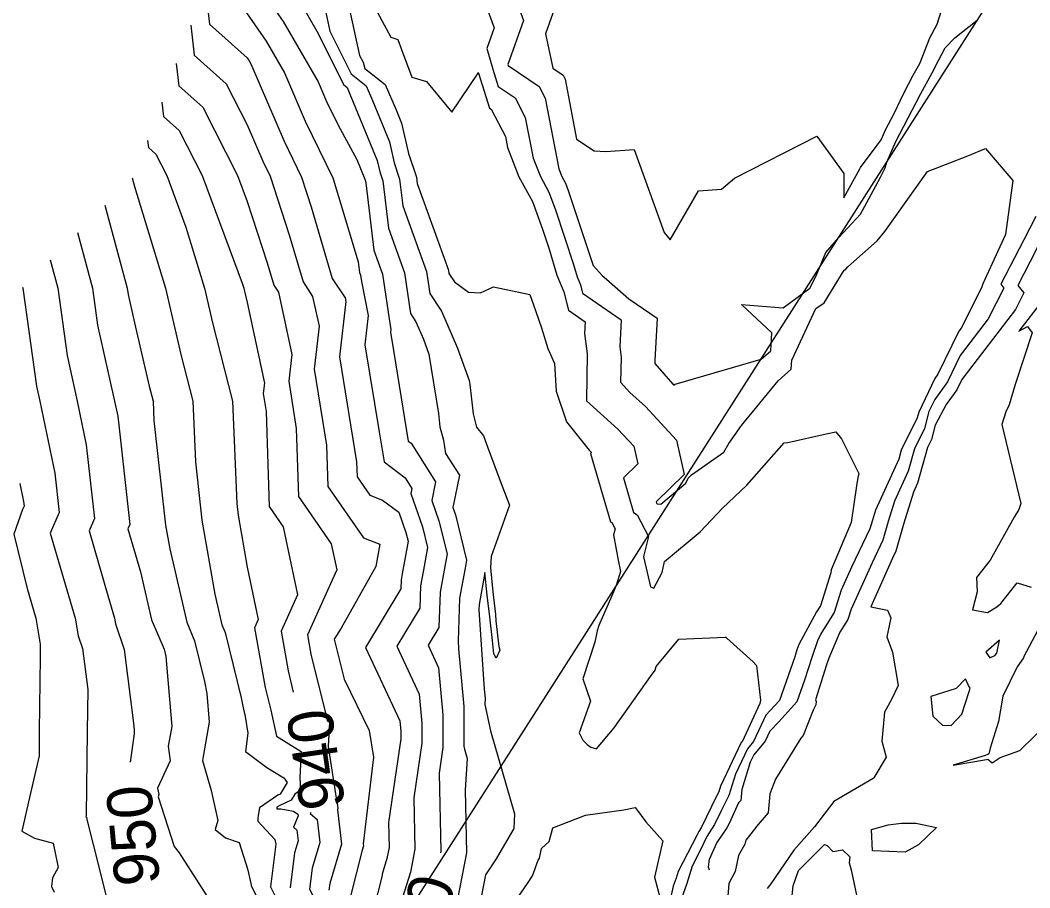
# Model space of a CAD drawing. Extents: x 1368651 to 1378602, y 762048 to 779328.
# Drawn here: x 1376956.1 to 1377179.9, y 762773.1 to 762965.4 of the extents above; entities that cross this region are included whole.
import ezdxf

# ---------------------------------------------------------------- set-up
doc = ezdxf.new("R2010")
doc.units = 0
for name, color, linetype in [('DTM Contours Major', 7, 'Continuous'), ('DTM Contours Major Text', 7, 'Continuous'), ('DTM Contours Minor', 7, 'Continuous'), ('Exist Plan Preparation Watershed Red', 7, 'Continuous')]:
    doc.layers.add(name, color=color, linetype=linetype)

msp = doc.modelspace()

# ---------------------------------------------------------------- linework, layer by layer
at = {"layer": 'DTM Contours Major'}
for points in [[(1377006.09, 762976.98), (1377014.37, 762965.06), (1377022.14, 762951.75), (1377024.01, 762947.39), (1377026.57, 762942.15), (1377030.74, 762934.5), (1377032.51, 762930.17), (1377032.62, 762929.71), (1377032.74, 762929.34), (1377034.51, 762914.39), (1377036.41, 762909.12), (1377038.08, 762897.71), (1377038.25, 762896.87), (1377038.17, 762896.15), (1377038.52, 762894), (1377042.1, 762872.08), (1377042.74, 762871.6), (1377048.17, 762863.08), (1377047.33, 762858.9), (1377048.91, 762854.41), (1377050.72, 762847.08), (1377050.06, 762843.49), (1377049.18, 762838.63), (1377048.9, 762830.79), (1377046.5, 762826.82), (1377048.84, 762821.84), (1377049.8, 762811.43), (1377049.77, 762804.13), (1377048.94, 762798.48), (1377049.31, 762781.19), (1377049.23, 762780.83)], [(1377058.99, 762969.52), (1377061.19, 762963.71), (1377059.54, 762959.08), (1377060.84, 762954.51), (1377062.04, 762950.7), (1377065.81, 762948.16), (1377068.06, 762943.84), (1377069.79, 762934.83), (1377071.4, 762930.71), (1377073.28, 762927.23), (1377074.73, 762923.34), (1377078.76, 762911.21), (1377079.54, 762908.5), (1377080.29, 762906.73), (1377080.75, 762904.84), (1377089.3, 762898.93), (1377088.98, 762892.96), (1377089.28, 762890.6), (1377089.19, 762885.16), (1377091.21, 762882.86), (1377094.7, 762879.72), (1377101.54, 762872.28), (1377103.27, 762864.67), (1377097.06, 762858.59), (1377097.15, 762858.3), (1377097.29, 762858.21), (1377098.13, 762858.12), (1377103.6, 762862.77), (1377104.16, 762863.9), (1377104.89, 762864.63), (1377112.03, 762869.6), (1377113.17, 762871.54), (1377115.99, 762875.57), (1377124.09, 762885.45), (1377127, 762888.01), (1377127.12, 762890.03), (1377132.47, 762901.47), (1377134.33, 762902.74), (1377138.71, 762909.97), (1377139.06, 762910.23), (1377139.51, 762910.73), (1377146.02, 762916.47), (1377147.71, 762918.51), (1377157.21, 762931.85), (1377166.15, 762935.31), (1377170.08, 762936.96), (1377175.21, 762930.91), (1377176.14, 762929.82), (1377174.5, 762917.91), (1377169.49, 762906.97), (1377169.14, 762906.07), (1377164.65, 762897.14), (1377164.11, 762896.43), (1377159.51, 762886.93), (1377158.82, 762885.97), (1377155.27, 762878.5), (1377154.94, 762877.26), (1377151.36, 762870.04), (1377150.82, 762868.09), (1377145.64, 762856.74), (1377144.97, 762854.59), (1377144.41, 762852.63), (1377140.36, 762844.15), (1377138.06, 762839.03), (1377136.51, 762834.06), (1377133.77, 762829.7), (1377132.87, 762828.06), (1377131.54, 762824.13), (1377129.95, 762819.09), (1377128.27, 762814.32), (1377124.22, 762809.84), (1377122.22, 762807.77), (1377121.2, 762805.58), (1377118.68, 762802.52), (1377117.93, 762800.93), (1377116.05, 762794.83), (1377115.81, 762792.45), (1377115.32, 762791.86), (1377113.27, 762787.3), (1377112.75, 762786.38), (1377110.54, 762783.13), (1377108.82, 762779.34), (1377108.57, 762777.74), (1377108.84, 762777.04)], [(1376987.53, 762947.24), (1376987.91, 762944.01), (1376991.38, 762940.9), (1376996.46, 762930.95), (1377005.31, 762907.07), (1377005.65, 762905.95), (1377005.8, 762905.32), (1377006.43, 762902.83), (1377010.24, 762884.94), (1377009.98, 762882.65), (1377010.64, 762878.61), (1377011.29, 762857.59), (1377014.4, 762853.1), (1377017.56, 762838.03), (1377013.92, 762829.93), (1377015.48, 762821.15), (1377016.63, 762816.45)], [(1376962.72, 762912.23), (1376964.42, 762905.95), (1376966.51, 762891.03), (1376968.77, 762880.95), (1376970.77, 762871.28), (1376972.6, 762854.95), (1376971.39, 762852.18), (1376975.56, 762837.83), (1376977.03, 762832.81), (1376977.24, 762831.61), (1376979.16, 762825.87), (1376981.3, 762808.97), (1376981.4, 762807.85), (1376981.35, 762807.6), (1376981.41, 762807.18), (1376980.49, 762800.89)], [(1377020.5, 762789.79), (1377020.38, 762789.5), (1377021.9, 762788.23), (1377022.53, 762783.11), (1377020.81, 762777.41), (1377020.23, 762772.77), (1377021.03, 762771.21), (1377021.67, 762765.13), (1377022.97, 762759.32), (1377022.92, 762758.41), (1377022.03, 762756.05), (1377021.79, 762755.12), (1377020.98, 762752.44), (1377011.76, 762733.51), (1377010.55, 762731.37), (1377010.02, 762730.1), (1377009.44, 762729.22), (1377005.89, 762721.26), (1377002.46, 762710.75), (1377002.26, 762709.63), (1377002.11, 762708.07), (1377001.81, 762707.06), (1376996.69, 762689.46), (1376996.41, 762688.23)]]:
    msp.add_lwpolyline(points, dxfattribs=at)
at = {"layer": 'DTM Contours Minor'}
for points in [[(1376997.08, 762972.78), (1376998.06, 762964.47), (1377006.41, 762957.01), (1377006.83, 762956.41), (1377007.22, 762955.74), (1377014.58, 762938.57), (1377018.46, 762930.62), (1377020.61, 762924.02), (1377025.28, 762908.14), (1377028.12, 762903.85), (1377028.28, 762903.03), (1377026.9, 762890.75), (1377030.66, 762867.51), (1377030.76, 762864.19), (1377033.61, 762860.08), (1377036.44, 762859.01), (1377040.02, 762856.32), (1377041.61, 762851.8), (1377042.08, 762849.88), (1377040.76, 762842.64), (1377040.53, 762841.36), (1377040.46, 762839.3), (1377032.63, 762826.36), (1377040.25, 762810.1), (1377040.47, 762807.75), (1377040.46, 762806.1), (1377037.75, 762787.54), (1377037.87, 762781.99), (1377037.38, 762779.54), (1377036.31, 762776.12), (1377036.3, 762775.77), (1377034.34, 762767.97)], [(1377022.97, 762971.3), (1377024.77, 762962.94), (1377029.43, 762953.49), (1377032.77, 762950.8), (1377034.16, 762947.62), (1377037.93, 762938.42), (1377038.99, 762933.77), (1377040.2, 762930.18), (1377040.91, 762924.24), (1377046.16, 762909.69), (1377046.87, 762904.8), (1377049.49, 762900.85), (1377053.06, 762892.67), (1377055.59, 762885.5), (1377055.73, 762884.64), (1377056.5, 762878.11), (1377057.26, 762875.2), (1377058.78, 762873.24), (1377059.66, 762870.81), (1377062.68, 762862.7), (1377064.56, 762857.87), (1377060.48, 762846.5), (1377060.34, 762844.01), (1377060.85, 762838.68), (1377061.48, 762833.62), (1377061.54, 762832.21), (1377062.19, 762826.56), (1377062.38, 762825.76), (1377061.61, 762823.98), (1377061.06, 762824.95), (1377060.77, 762827.91), (1377060.17, 762833.15), (1377059.58, 762837.91), (1377059.1, 762842.92), (1377057.84, 762835.89), (1377057.79, 762834.69), (1377058.94, 762817.11), (1377059.13, 762815.12), (1377059.12, 762813.73), (1377060.33, 762807.82), (1377065.69, 762789.49), (1377065.49, 762786.22), (1377061.59, 762779.49), (1377059.25, 762775.92), (1377058.29, 762771)], [(1377028.09, 762972.59), (1377031.33, 762957.53), (1377032.11, 762956.09), (1377032.51, 762954.7), (1377036.98, 762951.11), (1377039.42, 762945.51), (1377040.64, 762942.54), (1377042.17, 762935.8), (1377043.94, 762930.6), (1377044.11, 762929.17), (1377051.03, 762909.98), (1377051.14, 762909.24), (1377052.36, 762907.39), (1377055.45, 762905.12), (1377058.16, 762904.98), (1377061.01, 762906.28), (1377069.05, 762904.57), (1377070.37, 762900.83), (1377071.67, 762897.22), (1377073.05, 762892.63), (1377074.54, 762889.32), (1377074.93, 762883.18), (1377077.21, 762876.34), (1377082.2, 762870.04), (1377082.49, 762869.77), (1377082.64, 762869.61), (1377082.67, 762869.45), (1377082.54, 762869.33), (1377086.97, 762854.18), (1377087.2, 762854.04), (1377087.94, 762852.62), (1377087.63, 762851.31), (1377088.62, 762845.69), (1377089.18, 762843.15), (1377088.17, 762840.06), (1377087.18, 762837.67), (1377084.35, 762831.18), (1377083.97, 762830.05), (1377083.49, 762827.48), (1377080.79, 762819.38), (1377082.5, 762814.46), (1377080.01, 762807.43), (1377080.82, 762805.78), (1377081.74, 762804.83), (1377082.57, 762804.23), (1377083.84, 762803.83), (1377087.75, 762808.52), (1377095.83, 762819.87), (1377096.81, 762821.32), (1377097.08, 762822.14), (1377102.06, 762828.2), (1377112.34, 762828.61), (1377112.48, 762828.62), (1377112.5, 762828.6), (1377112.71, 762828.4), (1377118.53, 762823.16), (1377119.31, 762822.35), (1377120.16, 762814.63), (1377120.04, 762813.89), (1377116.09, 762805.44), (1377115.93, 762805.25), (1377111.34, 762795.59), (1377110.95, 762794.34), (1377110.53, 762793.49), (1377107.03, 762786.39), (1377106.5, 762785.56), (1377106.07, 762784.64), (1377101.92, 762776.7), (1377101.47, 762775.21), (1377100.83, 762773.39), (1377100, 762769.7)], [(1377018.14, 762969.38), (1377022.18, 762962.46), (1377027.75, 762951.14), (1377028.56, 762950.49), (1377028.9, 762949.72), (1377035.22, 762934.3), (1377035.8, 762931.74), (1377036.47, 762929.76), (1377037.71, 762919.31), (1377041.29, 762909.41), (1377042.61, 762900.37), (1377043.83, 762898.52), (1377045.49, 762894.71), (1377046.67, 762891.36), (1377048.79, 762878.22), (1377049.14, 762875.24), (1377049.9, 762872.32), (1377050.4, 762869.32), (1377053.44, 762864.56), (1377051.98, 762857.36), (1377052.56, 762855.71), (1377055.03, 762845.68), (1377054.71, 762843.91), (1377053.51, 762837.26), (1377053.17, 762827.82), (1377053.29, 762826), (1377054.46, 762813.27), (1377054.43, 762804.43), (1377054.56, 762803.78), (1377055.16, 762801.74), (1377054.73, 762794.75), (1377055.02, 762780.79), (1377053, 762770.56)], [(1377034.25, 762969.01), (1377038.24, 762961.65), (1377039.78, 762961.09), (1377040.64, 762958.91), (1377042.91, 762952.75), (1377046.15, 762951.8), (1377051.76, 762945.01), (1377057.6, 762953.66), (1377057.63, 762953.76), (1377057.66, 762953.64), (1377060.11, 762945.91), (1377060.5, 762945.65), (1377063.65, 762939.59), (1377064.11, 762937.2), (1377066.64, 762930.69), (1377069.62, 762925.21), (1377071.9, 762919.08), (1377073.38, 762914.6), (1377075.04, 762908.87), (1377076.62, 762905.14), (1377077.6, 762901.13), (1377081.34, 762898.55), (1377081.2, 762895.94), (1377081.76, 762891.43), (1377081.61, 762881.04), (1377081.65, 762880.99), (1377088.6, 762874.75), (1377092.09, 762870.95), (1377092.97, 762867.06), (1377089.8, 762863.96), (1377092.06, 762856.24), (1377092.83, 762855.77), (1377095.33, 762850.96), (1377094.29, 762846.52), (1377094.36, 762846.15), (1377095.77, 762839.76), (1377096.55, 762839.5), (1377098.4, 762842.92), (1377098.91, 762845.37), (1377106.83, 762851.97), (1377111.79, 762857.23), (1377117.19, 762862.33), (1377125.43, 762871.68), (1377126.23, 762871.76), (1377134.74, 762873.68), (1377136.85, 762874.15), (1377138.1, 762872.57), (1377141.99, 762864.87), (1377141.83, 762864.25), (1377141.79, 762864.05), (1377141.46, 762862.14), (1377140.29, 762854.05), (1377135.81, 762843.58), (1377135.74, 762842.9), (1377133.46, 762835.58), (1377132.62, 762834.26), (1377128.67, 762827.03), (1377128.26, 762825.81), (1377127.76, 762824.24), (1377124.36, 762814.55), (1377122.34, 762812.33), (1377121.35, 762811.3), (1377118.64, 762805.51), (1377117.31, 762803.89), (1377114.63, 762798.26), (1377113.16, 762793.51), (1377111.57, 762790.24), (1377110, 762787.07), (1377108.3, 762784.4), (1377106.91, 762781.45), (1377105.02, 762777.83), (1377103.86, 762774.03), (1377102.23, 762769.4)], [(1377066.24, 762969.14), (1377067.68, 762965.35), (1377064.18, 762955.56), (1377064.23, 762955.32), (1377071.13, 762950.67), (1377072.47, 762948.08), (1377075.48, 762932.46), (1377076.15, 762930.72), (1377076.95, 762929.25), (1377077.56, 762927.61), (1377083.08, 762910.98), (1377085.08, 762908.78), (1377086.03, 762907.99), (1377090.98, 762903.65), (1377097.26, 762899.31), (1377096.76, 762889.98), (1377096.79, 762889.76), (1377096.78, 762889.27), (1377100.77, 762884.73), (1377100.81, 762884.7), (1377101.07, 762884.42), (1377101.03, 762884.66), (1377101.25, 762884.71), (1377120.3, 762890.22), (1377122.46, 762892.12), (1377122.7, 762896.06), (1377116, 762902.35), (1377125.23, 762901.64), (1377131.12, 762905.97), (1377132.5, 762908.69), (1377134.68, 762913.92), (1377137.52, 762917.23), (1377142.36, 762922.4), (1377145.64, 762928.49), (1377146.79, 762930.58), (1377147.79, 762932.66), (1377148.18, 762933.93), (1377150.16, 762938.49), (1377154.72, 762947.14), (1377154.97, 762947.69), (1377155.23, 762948.17), (1377158.7, 762954.53), (1377158.98, 762955.22), (1377161.09, 762959.23), (1377163.24, 762961.47), (1377168.18, 762965.4)], [(1377074.16, 762966.98), (1377072.52, 762962.38), (1377074.15, 762954.73), (1377076.44, 762953.19), (1377076.89, 762952.32), (1377079.44, 762939.03), (1377083.31, 762936.4), (1377085.94, 762936.26), (1377092.16, 762936.7), (1377098.82, 762918.36), (1377100.16, 762916.73), (1377106.43, 762927.58), (1377111.51, 762927.95), (1377114.39, 762930.35), (1377132.69, 762939.7), (1377138.68, 762931.37), (1377138.67, 762926.04), (1377142.18, 762932.4), (1377142.35, 762932.76), (1377146.94, 762938.84), (1377147.97, 762941.2), (1377149.82, 762944.71), (1377151.92, 762949.21), (1377154.03, 762953.17), (1377155.46, 762955.79), (1377157.7, 762961.44), (1377159.31, 762964.48), (1377160.81, 762969.17)], [(1377006.25, 762967), (1377010.6, 762960.73), (1377014.68, 762953.74), (1377019.29, 762942.98), (1377025.42, 762930.43), (1377025.49, 762930.23), (1377026.64, 762926.29), (1377031.03, 762911.84), (1377031.32, 762909.46), (1377031.54, 762908.84), (1377031.74, 762907.48), (1377033.27, 762899.95), (1377032.53, 762893.45), (1377035.66, 762874.11), (1377036.75, 762867.45), (1377041.4, 762863.96), (1377042.91, 762861.6), (1377042.67, 762860.44), (1377045.26, 762853.11), (1377046.4, 762848.48), (1377045.41, 762843.07), (1377044.86, 762839.99), (1377044.68, 762835.05), (1377039.57, 762826.59), (1377044.54, 762815.97), (1377045.13, 762809.59), (1377045.12, 762805.12), (1377043.35, 762793.01), (1377043.59, 762781.59), (1377042.59, 762776.54), (1377040.38, 762769.51)], [(1376993.9, 762964.27), (1376994.68, 762957.65), (1377001.78, 762951.3), (1377006.43, 762942.18), (1377009.87, 762934.16), (1377011.5, 762930.81), (1377015.74, 762917.81), (1377018.8, 762907.39), (1377020.93, 762904.16), (1377022.34, 762897.58), (1377021.26, 762888.05), (1377023.98, 762871.21), (1377024.27, 762861.99), (1377032.17, 762850.61), (1377035.85, 762849.21), (1377034.95, 762844.31), (1377027.24, 762830.61), (1377025.69, 762828.21), (1377027.95, 762819.31), (1377033.48, 762807.95), (1377034.44, 762802.02), (1377032.15, 762782.78), (1377032.19, 762782.38), (1377031.9, 762781.41), (1377029.26, 762770.88)], [(1376990.71, 762955.76), (1376991.29, 762950.83), (1376996.58, 762946.1), (1377004.31, 762930.95), (1377006.43, 762925.22), (1377010.86, 762911.6), (1377012.33, 762906.63), (1377013.34, 762905.1), (1377016.29, 762891.26), (1377015.62, 762885.35), (1377017.31, 762874.91), (1377017.78, 762859.79), (1377025.05, 762849.31), (1377026.26, 762843.56), (1377019.78, 762829.13), (1377020.53, 762824.86), (1377024.04, 762810.59), (1377024.16, 762810.06), (1377024.66, 762809.75), (1377024.4, 762804.35), (1377026.16, 762792.95), (1377026.5, 762790.83), (1377026.44, 762790.31), (1377027.36, 762782.75), (1377024.73, 762774.02), (1377024.54, 762772.51)], [(1376984.34, 762938.73), (1376984.52, 762937.19), (1376986.18, 762935.7), (1376988.61, 762930.95), (1376992.84, 762919.54), (1376996.98, 762905.95), (1376998.77, 762898.29), (1377003.18, 762880.95), (1377004.12, 762858.26), (1377004.41, 762855.67), (1377006.43, 762844.12), (1377008.87, 762832.5), (1377008.07, 762830.72), (1377010.42, 762817.43), (1377011.65, 762812.41), (1377012.93, 762806.65), (1377018.37, 762803.28), (1377018.09, 762797.48), (1377018.26, 762794.68), (1377017.01, 762793.81), (1377016.2, 762792.49), (1377013.51, 762791.26), (1377013.02, 762790.93), (1377012.97, 762790.6), (1377013.86, 762790.56), (1377016.72, 762790.05), (1377017.62, 762789.4), (1377017.73, 762789.05), (1377016.69, 762786.47), (1377017.4, 762785.87), (1377017.69, 762783.47), (1377016.89, 762780.8), (1377015.91, 762773.02)], [(1376980.91, 762930.43), (1376981.43, 762928.52), (1376988.3, 762905.95), (1376991.75, 762891.27), (1376994.37, 762880.95), (1376994.93, 762867.45), (1376996.38, 762854.54), (1376999.24, 762838.17), (1377000.82, 762831.36), (1377001.55, 762829.63), (1377005.1, 762815.2), (1377005.37, 762813.71), (1377005.46, 762813.33), (1377005.97, 762811.03), (1377006.59, 762807.34), (1377006.06, 762803.28), (1377010.77, 762799.75), (1377014.53, 762797.41), (1377015.28, 762796.39), (1377013.7, 762793.8), (1377013.24, 762793.58), (1377009.13, 762790.81), (1377008.88, 762789.11), (1377008.77, 762788.52), (1377008.79, 762787.84), (1377012.53, 762783.8), (1377012.78, 762782.71), (1377011.59, 762773.27), (1377013.47, 762769.61)], [(1376974.85, 762924.36), (1376979.83, 762905.95), (1376980.03, 762904.55), (1376981.43, 762898.27), (1376984.72, 762884.24), (1376985.56, 762880.95), (1376985.73, 762876.64), (1376988.34, 762853.42), (1376989.26, 762848.2), (1376993.03, 762831.93), (1376994.77, 762827.8), (1376996.98, 762818.81), (1376997.46, 762816.15), (1376998.01, 762809.76), (1376996.72, 762802.58), (1376996.52, 762801.25), (1376998.43, 762794.65), (1376999.94, 762787.99), (1376999.32, 762786.01), (1377001.62, 762784.17), (1377004.65, 762783.09), (1377006.46, 762777.29), (1377007.3, 762773.69), (1377007.28, 762773.53), (1377009.7, 762768.81)], [(1377181.17, 762921.9), (1377178.52, 762916.67), (1377173.43, 762906.84), (1377174.09, 762906.01), (1377170.66, 762899.18), (1377164.45, 762891.08), (1377161.61, 762885.2), (1377158.8, 762881.3), (1377157.52, 762878.61), (1377156.52, 762874.87), (1377154.28, 762870.35), (1377152.91, 762865.41), (1377149.87, 762858.74), (1377148.47, 762854.25), (1377147.31, 762850.15), (1377144.91, 762845.12), (1377140.27, 762834.8), (1377139.56, 762832.54), (1377137.78, 762829.7), (1377135.33, 762823.98), (1377134.82, 762822.46), (1377132.39, 762814.74), (1377132.54, 762814.33), (1377132.44, 762813.64), (1377131.82, 762812.42), (1377129.67, 762806.82), (1377129.1, 762806.22), (1377123.49, 762797.13), (1377122.25, 762793.87), (1377121.85, 762789.67), (1377119.7, 762787.1), (1377116.94, 762783.62), (1377116.69, 762782.72), (1377115.29, 762780.2), (1377114.58, 762776.69), (1377113.13, 762774.04), (1377112.85, 762770.27)], [(1377185.41, 762922.7), (1377179.86, 762911.74), (1377177.2, 762906.61), (1377178.54, 762904.95), (1377176.67, 762901.23), (1377164.79, 762885.72), (1377163.7, 762883.48), (1377161.36, 762880.22), (1377158.93, 762875.58), (1377158.1, 762872.47), (1377157.2, 762870.66), (1377155.01, 762862.73), (1377154.1, 762860.73), (1377151.97, 762853.91), (1377150.21, 762847.67), (1377149.46, 762846.1), (1377144.64, 762835.38), (1377148.36, 762834.61), (1377149.04, 762832.91), (1377148.17, 762828.7), (1377149.41, 762825.26), (1377150.73, 762817.89), (1377149.19, 762814.81), (1377147.64, 762811.97), (1377147.08, 762805.55), (1377148.02, 762801.99), (1377145.32, 762797.41), (1377145.13, 762797.31), (1377136.41, 762792.22), (1377132.15, 762786.57), (1377127.54, 762781.42), (1377122.47, 762773.93), (1377121.68, 762772.87)], [(1376968.78, 762918.3), (1376972.12, 762905.95), (1376973.27, 762897.79), (1376977.03, 762880.95), (1376977.73, 762877.59), (1376980.42, 762853.61), (1376980, 762852.65), (1376982.78, 762843.08), (1376985.24, 762832.49), (1376987.99, 762825.97), (1376988.3, 762824.71), (1376988.37, 762824.33), (1376989.7, 762808.8), (1376988.92, 762804.43), (1376989.35, 762801.2), (1376986.55, 762795.13), (1376986.86, 762793.78), (1376986.69, 762793.25), (1376990.21, 762782.24), (1376991.32, 762780.82), (1376998.2, 762770.13)], [(1376956.65, 762906.17), (1376956.71, 762905.95), (1376959.75, 762884.27), (1376960.5, 762880.95), (1376963.81, 762864.98), (1376964.78, 762856.29), (1376962.78, 762851.7), (1376963.52, 762849.14), (1376968.31, 762832.81), (1376968.99, 762828.89), (1376969.92, 762826.1), (1376971.07, 762817.04), (1376970.94, 762807.8), (1376970.73, 762789.12), (1376970.66, 762788.78), (1376970.79, 762788.75), (1376970.9, 762788.21), (1376973.66, 762777.13), (1376976.76, 762764.61)], [(1377182.68, 762903.27), (1377177.44, 762896.44), (1377179.37, 762897.46), (1377180.4, 762896.11), (1377176.61, 762884.61), (1377175.33, 762880.15), (1377174.57, 762878.59), (1377173.64, 762875.79), (1377177.88, 762858.25), (1377177.47, 762856.94), (1377176.43, 762855.21), (1377171.07, 762845.71), (1377168.07, 762841.87), (1377168.21, 762838.67), (1377167.15, 762834.68), (1377170.47, 762834.06), (1377172.56, 762835.32), (1377173.45, 762836.09), (1377177.05, 762840.69), (1377180.18, 762839.68)], [(1376956.02, 762862.69), (1376956.85, 762858.67), (1376956.97, 762857.63), (1376956.64, 762856.89), (1376954.73, 762851.42), (1376957.65, 762839.39), (1376959.58, 762832.81), (1376960.57, 762827.07), (1376960.57, 762824.17), (1376960.35, 762807.81), (1376960.29, 762802.29), (1376958.18, 762793.07), (1376956.47, 762785.64), (1376959.27, 762784.09), (1376963.43, 762782.96), (1376964.51, 762777.58), (1376963.26, 762775.29), (1376963.03, 762773.38), (1376963.66, 762772.11)], [(1377181.54, 762830.01), (1377178.55, 762824.34), (1377178.49, 762824.05), (1377177.07, 762822.08), (1377173.9, 762815.52), (1377172.92, 762809.91), (1377171.08, 762804.03), (1377170.76, 762802.73), (1377170.55, 762802.62), (1377169.77, 762802.33), (1377162.91, 762800.23), (1377170.25, 762801.48), (1377170.58, 762801.57), (1377171.51, 762800.75), (1377173.33, 762801.96), (1377177.63, 762803.47), (1377184.3, 762809.98)], [(1377172.53, 762825.11), (1377173.12, 762827.97), (1377170.09, 762825.27), (1377170.99, 762824.06), (1377172.13, 762824.56), (1377172.53, 762825.11)], [(1377166.65, 762817.33), (1377166.3, 762817.88), (1377165.58, 762819.38), (1377163.57, 762817.21), (1377157.93, 762815.44), (1377158.39, 762811.1), (1377160.49, 762809.09), (1377162.44, 762809.04), (1377164.84, 762811.53), (1377166.45, 762816.54), (1377166.65, 762817.33)], [(1377065.92, 762770.15), (1377068.51, 762773.98), (1377069.69, 762775.68), (1377070.9, 762779.21), (1377071.17, 762779.65), (1377071.65, 762781.76), (1377073.33, 762783.29), (1377074.16, 762786.38), (1377081.4, 762789.18), (1377089.91, 762790.33), (1377092.4, 762790.85), (1377092.72, 762790.51), (1377094.76, 762787.7), (1377098.55, 762783.46), (1377096.66, 762775.39), (1377097.94, 762770.71)], [(1377144.98, 762781.28), (1377144.81, 762785.97), (1377148.48, 762787.04), (1377151.41, 762787.37), (1377154.59, 762787.37), (1377159.17, 762786.45), (1377155.19, 762782.57), (1377152.22, 762780.99), (1377144.98, 762781.28)], [(1377127.06, 762769.98), (1377127.4, 762773.48), (1377128.64, 762776.86), (1377134.38, 762782.69), (1377134.98, 762782.47), (1377136.25, 762781.13), (1377138.39, 762781.46), (1377140.01, 762779.93), (1377139.86, 762778.63), (1377140.28, 762777.07), (1377142.25, 762767.61)]]:
    msp.add_lwpolyline(points, dxfattribs=at)
at = {"layer": 'Exist Plan Preparation Watershed Red'}
msp.add_lwpolyline([(1373597.06, 767081.43), (1372938.47, 765818.8), (1372653.04, 765271.58), (1372900.45, 763223.22), (1372954.35, 762776.96), (1374508.77, 762195.85), (1375573.49, 762047.77), (1376441.31, 762392.26), (1376924.99, 762584.25), (1377201.49, 763017.52), (1377601.94, 763641.51), (1377736.1, 764021.28), (1377789.42, 764495.73), (1377827.52, 764834.78), (1378601.52, 765333.49), (1378471.1, 765535.9), (1378572.78, 766627.53)], dxfattribs=at)

# ---------------------------------------------------------------- texts
at = {"layer": 'DTM Contours Major Text'}
for s, rotation, p in [('940', 98.248, (1377028.18, 762791.16)), ('950', 95.4165, (1376987.14, 762774.01)), ('930', 75.2354, (1377047.08, 762752.6))]:
    msp.add_text(s, height=10, rotation=rotation, dxfattribs=at).set_placement(p)

doc.saveas('drawing.dxf')
